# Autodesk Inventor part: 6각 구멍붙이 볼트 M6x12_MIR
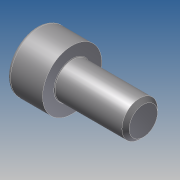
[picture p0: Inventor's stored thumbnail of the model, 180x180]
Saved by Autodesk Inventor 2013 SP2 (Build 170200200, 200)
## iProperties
Created: 2025-06
Part Number: 6각 구멍붙이 볼트 M6x12_MIR
Material: Generic
Document SubType Name: Modeling
Designer: i
Density: 1 g/cm^3
Author: i
변환 표준: STEP AP214IS
전처리기: Build: 200, Release: 2013 SP2 Update 6 - Date: Thu 07/17/2014
전송 단위: 밀리미터
불확실성: 0.01
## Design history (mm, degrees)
derived "6각 구멍붙이 볼트 M6x12.ipt"
feature "Solid1::6각 구멍붙이 볼트 M6x12.ipt" dims "d0" = 10
tag "피쳐 태그1"
node "솔리드1"
